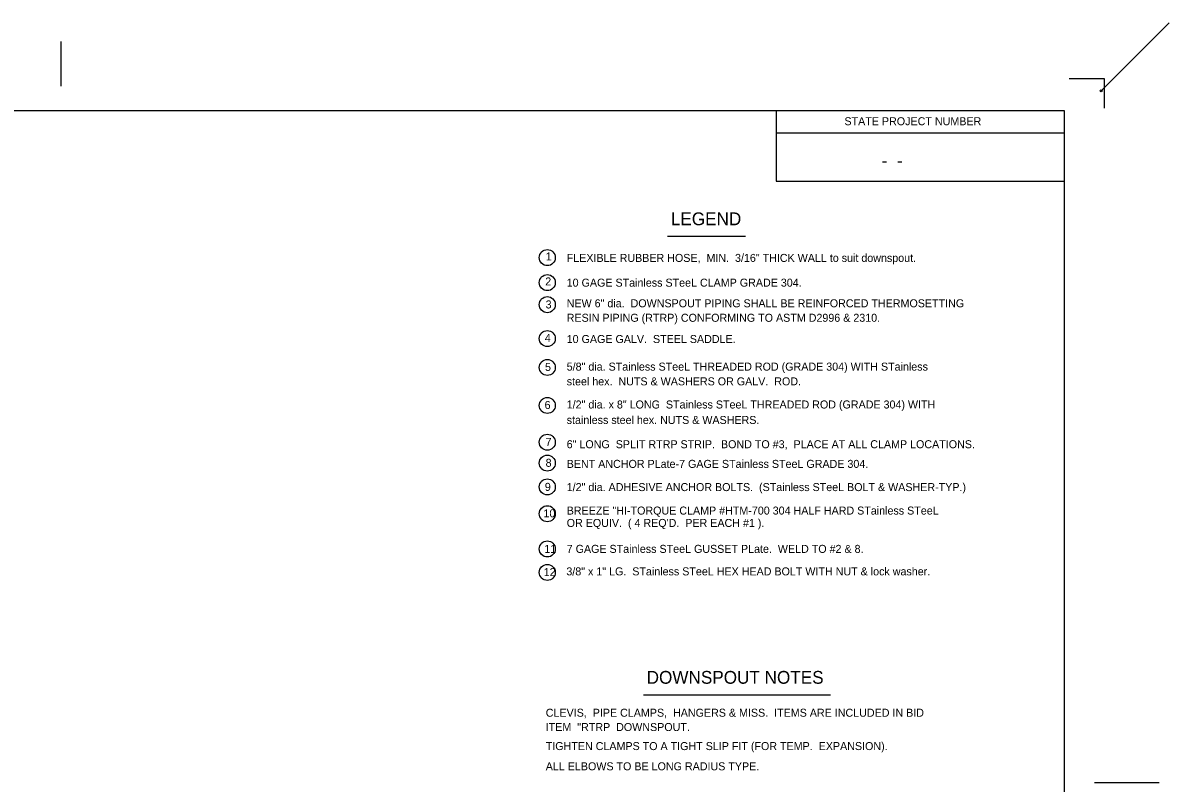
# Model space of a CAD drawing. Extents: x 15000 to 15012.1, y 999.8 to 1007.9.
# Drawn here: x 15006.08 to 15012.05, y 1003.78 to 1007.74 of the extents above; entities that cross this region are included whole.
import ezdxf

# ---------------------------------------------------------------- set-up
doc = ezdxf.new("R2010")
doc.units = 0
for name, color, linetype in [('Level 1', 7, 'Continuous'), ('Level 2', 7, 'Continuous'), ('Level 37', 7, 'Continuous'), ('Level 49', 7, 'Continuous')]:
    doc.layers.add(name, color=color, linetype=linetype)

msp = doc.modelspace()

# ---------------------------------------------------------------- linework, layer by layer
at = {"layer": 'Level 1'}
for p, q in [((15011.714, 1007.4479), (15011.5294, 1007.4479)), ((15011.714, 1007.2964), (15011.714, 1007.4479)), ((15011.5058, 1007.2814), (15001.0578, 1007.2814)), ((15010.0053, 1007.2814), (15010.0053, 1006.9166)), ((15011.5058, 1000.2885), (15011.5058, 1007.2814)), ((15010.0053, 1007.1667), (15011.5058, 1007.1667)), ((15010.0053, 1006.9166), (15011.5058, 1006.9166))]:
    msp.add_line(p, q, dxfattribs=at)
at = {"layer": 'Level 2'}
for p, q in [((15011.697, 1007.3865), (15012.0502, 1007.7397)), ((15009.4389, 1006.6292), (15009.8451, 1006.6292)), ((15009.3147, 1004.2419), (15010.2878, 1004.2419))]:
    msp.add_line(p, q, dxfattribs=at)
for centre in [(15008.8132, 1006.5177), (15008.8132, 1006.3875), (15008.8132, 1006.2729), (15008.8132, 1006.0963), (15008.8132, 1005.9458), (15008.8132, 1005.748), (15008.8132, 1005.5565), (15008.8132, 1005.4481), (15008.8132, 1005.3241), (15008.8132, 1005.1846), (15008.8132, 1005.001), (15008.8132, 1004.8789)]:
    msp.add_circle(centre, 0.0417, dxfattribs=at)
at = {"layer": 'Level 37'}
for p, q in [((15006.2818, 1007.4105), (15006.2818, 1007.6437)), ((15011.6624, 1003.7849), (15011.9988, 1003.7849))]:
    msp.add_line(p, q, dxfattribs=at)
at = {"layer": 'Level 49'}
msp.add_circle((15011.6969, 1007.3865), 0.00506, dxfattribs=at)

# ---------------------------------------------------------------- texts
at = {"layer": 'Level 1'}
for s, height, p in [('STATE PROJECT NUMBER', 0.041708, (15010.36, 1007.2069)), ('    -  -  ', 0.06735, (15010.4538, 1006.9895))]:
    msp.add_text(s, height=height, dxfattribs=at).set_placement(p)
at = {"layer": 'Level 2'}
for s, height, p in [('LEGEND', 0.06667, (15009.4564, 1006.6865)), ('1', 0.0417, (15008.805, 1006.5031)), ('FLEXIBLE RUBBER HOSE,  MIN.  3/16" THICK WALL to suit downspout.', 0.041667, (15008.9141, 1006.4954)), ('2', 0.0417, (15008.8025, 1006.3729)), ('10 GAGE STainless STeeL CLAMP GRADE 304.', 0.041667, (15008.9141, 1006.3666)), ('3', 0.0417, (15008.8042, 1006.2532)), ('NEW 6" dia.  DOWNSPOUT PIPING SHALL BE REINFORCED THERMOSETTING', 0.041667, (15008.9141, 1006.2592)), ('RESIN PIPING (RTRP) CONFORMING TO ASTM D2996 & 2310.', 0.041667, (15008.9141, 1006.1838)), ('4', 0.0417, (15008.8003, 1006.0793)), ('10 GAGE GALV.  STEEL SADDLE.', 0.041667, (15008.9141, 1006.0731)), ('5', 0.0417, (15008.8013, 1005.9277)), ('5/8" dia. STainless STeeL THREADED ROD (GRADE 304) WITH STainless', 0.041667, (15008.9141, 1005.9295)), ('steel hex.  NUTS & WASHERS OR GALV.  ROD.', 0.041667, (15008.9141, 1005.8527)), ('6', 0.0417, (15008.799, 1005.7298)), ('1/2" dia. x 8" LONG  STainless STeeL THREADED ROD (GRADE 304) WITH', 0.041667, (15008.9141, 1005.7323)), ('stainless steel hex. NUTS & WASHERS. ', 0.041667, (15008.9141, 1005.6518)), ('7', 0.0417, (15008.804, 1005.5372)), ('6" LONG  SPLIT RTRP STRIP.  BOND TO #3,  PLACE AT ALL CLAMP LOCATIONS.', 0.041667, (15008.9141, 1005.5254)), ('8', 0.0417, (15008.8043, 1005.4288)), ('BENT ANCHOR PLate-7 GAGE STainless STeeL GRADE 304.', 0.041667, (15008.9141, 1005.4231)), ('9', 0.0417, (15008.8003, 1005.3034)), ('1/2" dia. ADHESIVE ANCHOR BOLTS.  (STainless STeeL BOLT & WASHER-TYP.)', 0.041667, (15008.9141, 1005.3023)), ('10', 0.04167, (15008.7931, 1005.1657)), ('BREEZE "HI-TORQUE CLAMP #HTM-700 304 HALF HARD STainless STeeL', 0.041667, (15008.9141, 1005.18)), ("OR EQUIV.  ( 4 REQ'D.  PER EACH #1 ).", 0.041667, (15008.9141, 1005.1156)), ('11', 0.04167, (15008.7978, 1004.9807)), ('7 GAGE STainless STeeL GUSSET PLate.  WELD TO #2 & 8.', 0.041667, (15008.9141, 1004.9806)), ('12', 0.04167, (15008.7944, 1004.86)), ('3/8" x 1" LG.  STainless STeeL HEX HEAD BOLT WITH NUT & lock washer.', 0.041667, (15008.9124, 1004.8634)), ('DOWNSPOUT NOTES', 0.066667, (15009.3304, 1004.2992)), ('CLEVIS,  PIPE CLAMPS,  HANGERS & MISS.  ITEMS ARE INCLUDED IN BID', 0.041667, (15008.805, 1004.1275)), ('ITEM  "RTRP  DOWNSPOUT.', 0.041667, (15008.805, 1004.0531)), ('TIGHTEN CLAMPS TO A TIGHT SLIP FIT (FOR TEMP.  EXPANSION).', 0.041667, (15008.805, 1003.9539)), ('ALL ELBOWS TO BE LONG RADIUS TYPE.', 0.041667, (15008.805, 1003.8486))]:
    msp.add_text(s, height=height, dxfattribs=at).set_placement(p)

doc.saveas('drawing.dxf')
